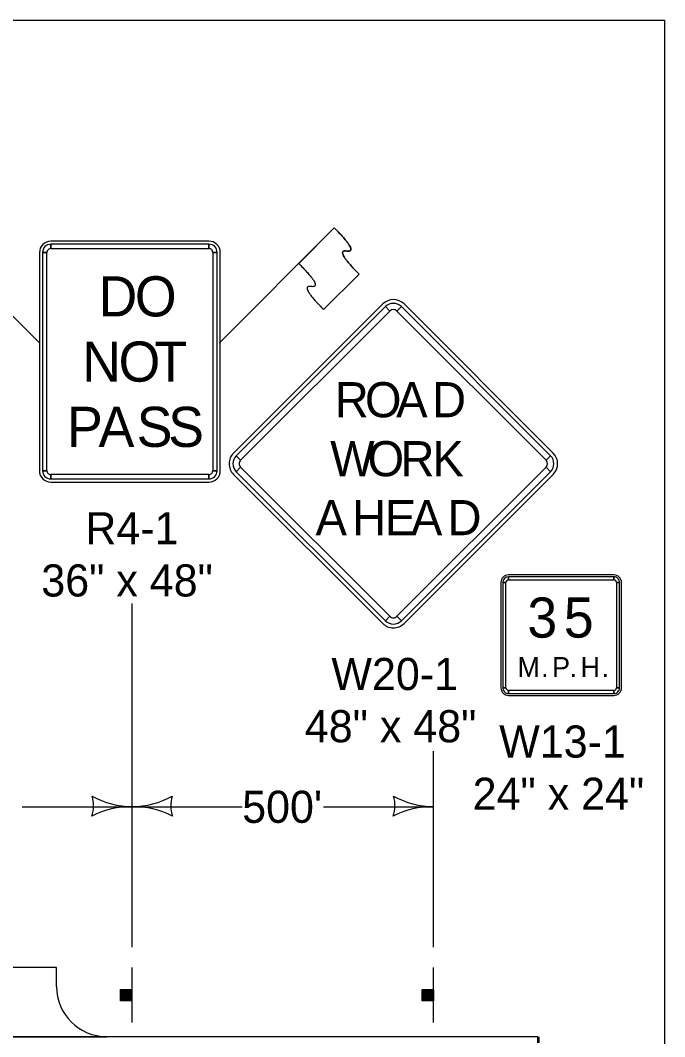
# Model space of a CAD drawing. Extents: x -2134934 to -2122394, y -2140205 to -2137036.
# Drawn here: x -2127418 to -2127097, y -2137542 to -2137036 of the extents above; entities that cross this region are included whole.
import ezdxf

# ---------------------------------------------------------------- set-up
doc = ezdxf.new("R2010")
doc.units = 0
for name, color, linetype in [('Barrier', 7, 'Continuous'), ('BridgeSuperStructureExisting', 7, 'Continuous'), ('Default', 7, 'Continuous'), ('DsnShtPlotIdentification', 7, 'Continuous'), ('TC_Barrier', 7, 'Continuous')]:
    doc.layers.add(name, color=color, linetype=linetype)

msp = doc.modelspace()

# ---------------------------------------------------------------- linework, layer by layer
at = {"layer": 'Barrier'}
for p, q in [((-2127407.97, -2137196.68), (-2127465.31, -2137139.38)), ((-2127318.68, -2137196.68), (-2127261.36, -2137139.36)), ((-2127261.36, -2137139.36), (-2127279.05, -2137157.04)), ((-2127323.73, -2137145.92), (-2127402.48, -2137145.92)), ((-2127402.48, -2137149.67), (-2127402.48, -2137147.48)), ((-2127323.73, -2137147.48), (-2127323.73, -2137149.67)), ((-2127408.11, -2137151.54), (-2127408.11, -2137260.29)), ((-2127406.54, -2137151.54), (-2127404.36, -2137151.54)), ((-2127321.86, -2137151.54), (-2127319.67, -2137151.54)), ((-2127318.11, -2137260.29), (-2127318.11, -2137151.54)), ((-2127266.66, -2137180.03), (-2127248.99, -2137162.35)), ((-2127237.26, -2137177.23), (-2127311.51, -2137251.47)), ((-2127152.41, -2137251.47), (-2127226.65, -2137177.23)), ((-2127235.93, -2137178.55), (-2127233.72, -2137180.76)), ((-2127230.19, -2137180.76), (-2127227.98, -2137178.55)), ((-2127307.97, -2137255.01), (-2127310.18, -2137252.8)), ((-2127153.73, -2137252.8), (-2127155.94, -2137255.01)), ((-2127310.18, -2137260.75), (-2127307.97, -2137258.54)), ((-2127155.94, -2137258.54), (-2127153.73, -2137260.75)), ((-2127404.36, -2137260.29), (-2127406.54, -2137260.29)), ((-2127402.48, -2137264.35), (-2127402.48, -2137262.17)), ((-2127323.73, -2137262.17), (-2127323.73, -2137264.35)), ((-2127319.67, -2137260.29), (-2127321.86, -2137260.29)), ((-2127311.51, -2137262.08), (-2127237.26, -2137336.33)), ((-2127226.65, -2137336.33), (-2127152.41, -2137262.08)), ((-2127402.48, -2137265.92), (-2127323.73, -2137265.92)), ((-2127122.19, -2137312.17), (-2127174.69, -2137312.17)), ((-2127174.69, -2137314.67), (-2127174.69, -2137313.1)), ((-2127122.19, -2137313.1), (-2127122.19, -2137314.67)), ((-2127178.44, -2137315.92), (-2127178.44, -2137368.42)), ((-2127177.5, -2137315.92), (-2127175.94, -2137315.92)), ((-2127120.94, -2137315.92), (-2127119.37, -2137315.92)), ((-2127118.44, -2137368.42), (-2127118.44, -2137315.92)), ((-2127233.72, -2137332.79), (-2127235.93, -2137335)), ((-2127227.98, -2137335), (-2127230.19, -2137332.79)), ((-2127175.94, -2137368.42), (-2127177.5, -2137368.42)), ((-2127174.69, -2137371.23), (-2127174.69, -2137369.67)), ((-2127122.19, -2137369.67), (-2127122.19, -2137371.23)), ((-2127119.37, -2137368.42), (-2127120.94, -2137368.42)), ((-2127174.69, -2137372.17), (-2127122.19, -2137372.17))]:
    msp.add_line(p, q, dxfattribs=at)
for points in [[(-2127323.73, -2137147.48), (-2127402.48, -2137147.48), (-2127402.48, -2137149.67), (-2127323.73, -2137149.67), (-2127323.73, -2137147.48)], [(-2127406.54, -2137151.54), (-2127406.54, -2137260.29), (-2127404.36, -2137260.29), (-2127404.36, -2137151.54), (-2127406.54, -2137151.54)], [(-2127319.67, -2137260.29), (-2127319.67, -2137151.54), (-2127321.86, -2137151.54), (-2127321.86, -2137260.29), (-2127319.67, -2137260.29)], [(-2127235.93, -2137178.55), (-2127310.18, -2137252.8), (-2127307.97, -2137255.01), (-2127233.72, -2137180.76), (-2127235.93, -2137178.55)], [(-2127153.73, -2137252.8), (-2127227.98, -2137178.55), (-2127230.19, -2137180.76), (-2127155.94, -2137255.01), (-2127153.73, -2137252.8)], [(-2127310.18, -2137260.75), (-2127235.93, -2137335), (-2127233.72, -2137332.79), (-2127307.97, -2137258.54), (-2127310.18, -2137260.75)], [(-2127227.98, -2137335), (-2127153.73, -2137260.75), (-2127155.94, -2137258.54), (-2127230.19, -2137332.79), (-2127227.98, -2137335)], [(-2127402.48, -2137264.35), (-2127323.73, -2137264.35), (-2127323.73, -2137262.17), (-2127402.48, -2137262.17), (-2127402.48, -2137264.35)], [(-2127122.19, -2137313.1), (-2127174.69, -2137313.1), (-2127174.69, -2137314.67), (-2127122.19, -2137314.67), (-2127122.19, -2137313.1)], [(-2127177.5, -2137315.92), (-2127177.5, -2137368.42), (-2127175.94, -2137368.42), (-2127175.94, -2137315.92), (-2127177.5, -2137315.92)], [(-2127119.37, -2137368.42), (-2127119.37, -2137315.92), (-2127120.94, -2137315.92), (-2127120.94, -2137368.42), (-2127119.37, -2137368.42)], [(-2127174.69, -2137371.23), (-2127122.19, -2137371.23), (-2127122.19, -2137369.67), (-2127174.69, -2137369.67), (-2127174.69, -2137371.23)]]:
    msp.add_lwpolyline(points, close=True, dxfattribs=at)
for centre, radius, start, end in [((-2127402.48, -2137151.54), 5.62, 90.0002, 179.9998), ((-2127402.48, -2137151.54), 4.06, 90.0002, 179.9998), ((-2127323.73, -2137151.54), 5.62, 0, 90.0002), ((-2127323.73, -2137151.54), 4.06, 0, 90.0002), ((-2127402.48, -2137151.54), 1.87, 90.0002, 179.9998), ((-2127323.73, -2137151.54), 1.87, 0, 90.0002), ((-2127231.96, -2137182.53), 7.5, 45, 134.9997), ((-2127231.96, -2137182.53), 5.62, 45, 134.9997), ((-2127231.96, -2137182.53), 2.5, 45, 134.9997), ((-2127306.2, -2137256.78), 7.5, 134.9997, 225), ((-2127306.2, -2137256.78), 5.62, 134.9997, 225), ((-2127157.71, -2137256.78), 5.62, 315.0002, 44.9998), ((-2127157.71, -2137256.78), 7.5, 315.0002, 44.9998), ((-2127306.2, -2137256.78), 2.5, 134.9997, 225), ((-2127157.71, -2137256.78), 2.5, 315.0002, 44.9998), ((-2127402.48, -2137260.29), 5.62, 179.9998, 270.0001), ((-2127402.48, -2137260.29), 4.06, 179.9998, 270.0001), ((-2127402.48, -2137260.29), 1.87, 179.9998, 270.0001), ((-2127323.73, -2137260.29), 5.62, 270.0001, 0.0003), ((-2127323.73, -2137260.29), 4.06, 270.0001, 0.0003), ((-2127323.73, -2137260.29), 1.87, 270.0001, 0.0003), ((-2127174.69, -2137315.92), 3.75, 90.0002, 179.9998), ((-2127174.69, -2137315.92), 2.81, 90.0002, 179.9998), ((-2127174.69, -2137315.92), 1.25, 90.0002, 179.9998), ((-2127122.19, -2137315.92), 3.75, 0, 90.0002), ((-2127122.19, -2137315.92), 2.81, 0, 90.0002), ((-2127122.19, -2137315.92), 1.25, 0, 90.0002), ((-2127231.96, -2137331.02), 5.62, 225, 315.0002), ((-2127231.96, -2137331.02), 2.5, 225, 315.0002), ((-2127231.96, -2137331.02), 7.5, 225, 315.0002), ((-2127174.69, -2137368.42), 3.75, 179.9998, 270.0001), ((-2127174.69, -2137368.42), 2.81, 179.9998, 270.0001), ((-2127174.69, -2137368.42), 1.25, 179.9998, 270.0001), ((-2127122.19, -2137368.42), 3.75, 270.0001, 0.0003), ((-2127122.19, -2137368.42), 2.81, 270.0001, 0.0003), ((-2127122.19, -2137368.42), 1.25, 270.0001, 0.0003)]:
    msp.add_arc(centre, radius, start, end, dxfattribs=at)
for points in [[(-2127248.99, -2137162.35), (-2127261.36, -2137149.98), (-2127248.99, -2137151.75), (-2127261.36, -2137139.36)], [(-2127279.05, -2137157.04), (-2127266.67, -2137169.43), (-2127279.04, -2137167.66), (-2127266.66, -2137180.03)]]:
    msp.add_open_spline(points, degree=2, dxfattribs=at)
at = {"layer": 'BridgeSuperStructureExisting'}
for p, q in [((-2127361.96, -2137497.66), (-2127361.96, -2137326.42)), ((-2127211.96, -2137497.66), (-2127211.96, -2137399.97)), ((-2127416.71, -2137427.66), (-2127361.96, -2137427.66)), ((-2127361.96, -2137427.66), (-2127307.21, -2137427.66)), ((-2127266.71, -2137427.66), (-2127211.96, -2137427.66)), ((-2127361.96, -2137535.16), (-2127361.96, -2137507.66)), ((-2127211.96, -2137535.16), (-2127211.96, -2137507.66)), ((-2127367.28, -2137524.3), (-2127367.28, -2137518.71)), ((-2127366.96, -2137518.71), (-2127366.96, -2137524.3)), ((-2127366.74, -2137524.3), (-2127366.74, -2137518.71)), ((-2127366.42, -2137518.71), (-2127366.42, -2137524.3)), ((-2127366.19, -2137524.3), (-2127366.21, -2137518.71)), ((-2127365.78, -2137518.71), (-2127365.76, -2137524.3)), ((-2127365.56, -2137524.3), (-2127365.56, -2137518.71)), ((-2127365.13, -2137518.71), (-2127365.13, -2137524.3)), ((-2127364.75, -2137524.3), (-2127364.75, -2137518.71)), ((-2127364.43, -2137518.71), (-2127364.41, -2137524.3)), ((-2127364.21, -2137524.3), (-2127364.21, -2137518.71)), ((-2127363.94, -2137518.71), (-2127363.94, -2137524.3)), ((-2127363.61, -2137524.3), (-2127363.61, -2137518.71)), ((-2127363.4, -2137518.71), (-2127363.4, -2137524.3)), ((-2127363.18, -2137524.3), (-2127363.18, -2137518.71)), ((-2127362.91, -2137518.71), (-2127362.91, -2137524.3)), ((-2127362.65, -2137524.3), (-2127362.65, -2137518.71)), ((-2127362.37, -2137518.71), (-2127362.37, -2137524.3)), ((-2127217.28, -2137524.3), (-2127217.28, -2137518.71)), ((-2127216.96, -2137518.71), (-2127216.96, -2137524.3)), ((-2127216.74, -2137524.3), (-2127216.74, -2137518.71)), ((-2127216.42, -2137518.71), (-2127216.42, -2137524.3)), ((-2127216.2, -2137524.3), (-2127216.21, -2137518.71)), ((-2127215.78, -2137518.71), (-2127215.76, -2137524.3)), ((-2127215.56, -2137524.3), (-2127215.56, -2137518.71)), ((-2127215.13, -2137518.71), (-2127215.13, -2137524.3)), ((-2127214.75, -2137524.3), (-2127214.75, -2137518.71)), ((-2127214.43, -2137518.71), (-2127214.41, -2137524.3)), ((-2127214.21, -2137524.3), (-2127214.21, -2137518.71)), ((-2127213.94, -2137518.71), (-2127213.94, -2137524.3)), ((-2127213.61, -2137524.3), (-2127213.61, -2137518.71)), ((-2127213.4, -2137518.71), (-2127213.4, -2137524.3)), ((-2127213.18, -2137524.3), (-2127213.18, -2137518.71)), ((-2127212.91, -2137518.71), (-2127212.91, -2137524.3)), ((-2127212.65, -2137524.3), (-2127212.65, -2137518.71)), ((-2127212.37, -2137518.71), (-2127212.37, -2137524.3)), ((-2127484.56, -2137542.16), (-2127374.56, -2137542.16))]:
    msp.add_line(p, q, dxfattribs=at)
msp.add_lwpolyline([(-2127399.56, -2137517.16), (-2127399.56, -2137507.67), (-2127459.56, -2137507.67), (-2127459.56, -2137517.16)], dxfattribs=at)
for points in [[(-2127362.05, -2137518.71), (-2127362.05, -2137524.34), (-2127367.68, -2137524.34), (-2127367.68, -2137518.71)], [(-2127212.05, -2137518.71), (-2127212.05, -2137524.34), (-2127217.68, -2137524.34), (-2127217.68, -2137518.71)]]:
    msp.add_lwpolyline(points, close=True, dxfattribs=at)
for centre, radius, start, end in [((-2127397.57, -2137427.04), 16.42, 341.2666, 16.7334), ((-2127361.2, -2137385.17), 42.5, 240.9275, 268.9824), ((-2127362.71, -2137385.17), 42.5, 271.0176, 299.0725), ((-2127326.34, -2137427.04), 16.42, 163.2666, 198.7334), ((-2127247.57, -2137427.04), 16.42, 341.2666, 16.7334), ((-2127211.2, -2137385.17), 42.5, 240.9275, 268.9824), ((-2127362.68, -2137470.15), 42.5, 89.0176, 117.0725), ((-2127361.23, -2137470.15), 42.5, 62.9275, 90.9824), ((-2127212.68, -2137470.15), 42.5, 89.0176, 117.0725), ((-2127374.56, -2137517.16), 25, 180, 270)]:
    msp.add_arc(centre, radius, start, end, dxfattribs=at)
at = {"layer": 'Default'}
msp.add_lwpolyline([(-2130231.95, -2137035.95), (-2127096.96, -2137035.95), (-2127096.96, -2139045.94), (-2130231.95, -2139045.94)], close=True, dxfattribs=at)
at = {"layer": 'DsnShtPlotIdentification'}
for p, q in [((-2127160.12, -2137542.16), (-2128660.12, -2137542.16)), ((-2127160.12, -2137542.16), (-2128660.12, -2137542.16)), ((-2127160.12, -2137545.16), (-2127160.12, -2137542.16)), ((-2127159.5, -2137542.16), (-2127159.5, -2137545.16))]:
    msp.add_line(p, q, dxfattribs=at)
at = {"layer": 'TC_Barrier'}
msp.add_line((-2127248.99, -2137162.35), (-2127266.66, -2137180.03), dxfattribs=at)
for points in [[(-2127261.36, -2137139.36), (-2127248.99, -2137151.75), (-2127261.36, -2137149.98), (-2127248.99, -2137162.35)], [(-2127279.05, -2137157.04), (-2127266.67, -2137169.43), (-2127279.04, -2137167.66), (-2127266.66, -2137180.03)]]:
    msp.add_open_spline(points, degree=2, dxfattribs=at)

# ---------------------------------------------------------------- texts
at = {"layer": 'Barrier'}
for s, height, p in [('O', 20, (-2127360.61, -2137183.42)), ('D', 20, (-2127378.73, -2137183.42)), ('N', 20, (-2127386.86, -2137215.92)), ('O', 20, (-2127368.73, -2137215.92)), ('T', 20, (-2127350.92, -2137215.92)), ('R', 17.5, (-2127261.12, -2137233.65)), ('O', 17.5, (-2127246.11, -2137233.65)), ('A', 17.5, (-2127230.56, -2137233.65)), ('D', 17.5, (-2127212.68, -2137233.65)), ('P', 20, (-2127394.37, -2137248.42)), ('A', 20, (-2127378.69, -2137248.42)), ('S', 20, (-2127359.72, -2137248.42)), ('S', 20, (-2127344.03, -2137248.42)), ('W', 17.5, (-2127263.4, -2137263.03)), ('O', 17.5, (-2127244.81, -2137263.03)), ('R', 17.5, (-2127228.4, -2137263.03)), ('K', 17.5, (-2127212.54, -2137263.03)), ('A', 17.5, (-2127270.68, -2137292.4)), ('H', 17.5, (-2127252.47, -2137292.4)), ('E', 17.5, (-2127236.24, -2137292.4)), ('A', 17.5, (-2127223.2, -2137292.4)), ('D', 17.5, (-2127204.99, -2137292.4)), ('R4-1', 16, (-2127385.27, -2137296.92)), ('36" x 48"', 16, (-2127407.17, -2137322.92)), ('3', 20, (-2127165.29, -2137343.41)), ('5', 20, (-2127147.16, -2137343.41)), ('W20-1', 16, (-2127262.81, -2137369.52)), ('M', 10, (-2127170.21, -2137363.1)), ('P', 10, (-2127152.96, -2137363.1)), ('H', 10, (-2127138.84, -2137363.1)), ('.', 10, (-2127158.42, -2137363.1)), ('.', 10, (-2127144.3, -2137363.1)), ('.', 10, (-2127128.37, -2137363.1)), ('48" x 48"', 16, (-2127276.02, -2137395.52)), ('W13-1', 16, (-2127179.29, -2137403.17)), ('24" x 24"', 16, (-2127192.5, -2137429.17))]:
    msp.add_text(s, height=height, dxfattribs=at).set_placement(p)
at = {"layer": 'BridgeSuperStructureExisting'}
msp.add_text("500'", height=16, dxfattribs=at).set_placement((-2127307.21, -2137435.66))

doc.saveas('drawing.dxf')
